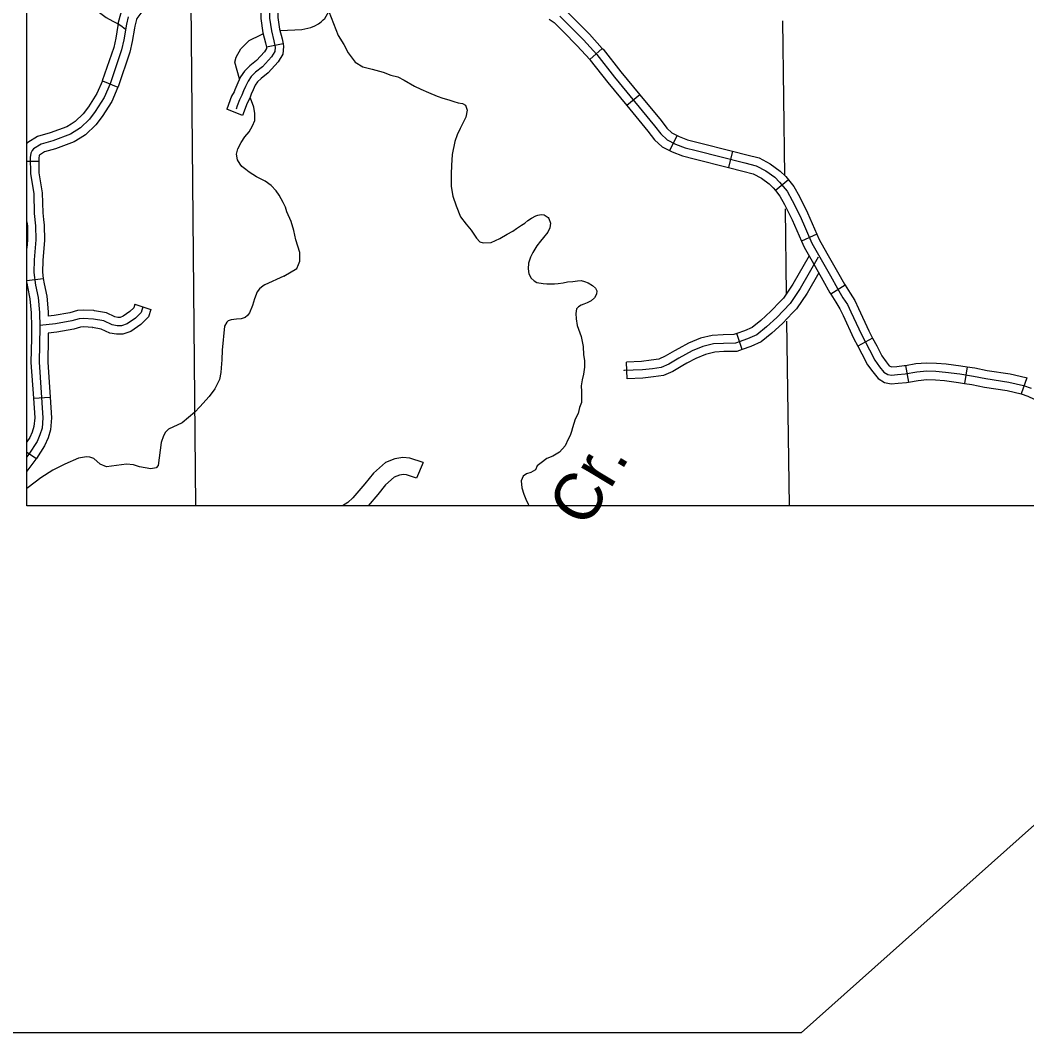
# Model space of a CAD drawing. Extents: x 1377389 to 1380723, y 1168351 to 1170484.
# Drawn here: x 1378339.4 to 1378518.7, y 1168608.3 to 1168788.5 of the extents above; entities that cross this region are included whole.
import ezdxf

# ---------------------------------------------------------------- set-up
doc = ezdxf.new("R2010")
doc.units = 0
for name, color, linetype in [('B_Contour_Elevations', 7, 'Continuous'), ('B_Fill', 7, 'Continuous'), ('B_Text', 7, 'Continuous')]:
    doc.layers.add(name, color=color, linetype=linetype)

msp = doc.modelspace()

# ---------------------------------------------------------------- linework, layer by layer
at = {"layer": 'B_Contour_Elevations'}
for q in [(1379068.4, 1169134.14), (1378016.6, 1168608.3)]:
    msp.add_line((1378478.5, 1168608.3), q, dxfattribs=at)
at = {"layer": 'B_Fill'}
for p, q in [((1378386.22, 1168784.29), (1378383.28, 1168783.71)), ((1378443.07, 1168783.5), (1378440.83, 1168781.5)), ((1378354.05, 1168777.75), (1378356.81, 1168776.57)), ((1378449.74, 1168775.25), (1378447.43, 1168773.33)), ((1378378.99, 1168771.54), (1378376.21, 1168772.67)), ((1378456.43, 1168767.97), (1378455.04, 1168765.31)), ((1378466.24, 1168765.22), (1378465.52, 1168762.3)), ((1378340.61, 1168763.4), (1378342.75, 1168763.41)), ((1378476.23, 1168760.1), (1378473.92, 1168758.18)), ((1378481.3, 1168750.42), (1378478.55, 1168749.21)), ((1378340.61, 1168742.19), (1378343.53, 1168742.56)), ((1378486.3, 1168741.35), (1378483.74, 1168739.78)), ((1378359.85, 1168737.96), (1378362.69, 1168737.02)), ((1378468, 1168729.9), (1378467.01, 1168732.73)), ((1378491.21, 1168731.91), (1378488.55, 1168730.52)), ((1378447.47, 1168724.68), (1378447.36, 1168727.68)), ((1378497.06, 1168727.07), (1378497.58, 1168724.11)), ((1378508.02, 1168726.84), (1378507.56, 1168723.87)), ((1378518.65, 1168724.86), (1378517.68, 1168722.02)), ((1378341.76, 1168721.23), (1378344.75, 1168721.44)), ((1378340.61, 1168711.63), (1378342.29, 1168710.53))]:
    msp.add_line(p, q, dxfattribs=at)
for points in [[(1378370.69, 1168702.1), (1378369.82, 1168798.09), (1378369.77, 1168801.63)], [(1378362.4, 1168796.94), (1378362.58, 1168795.29), (1378362.53, 1168794.06), (1378362.12, 1168791.97), (1378361.65, 1168790.93), (1378360.91, 1168789.75), (1378360.2, 1168788.83), (1378360.11, 1168788.62), (1378359.82, 1168787.47), (1378359.75, 1168787.07)], [(1378384.73, 1168795.78), (1378382.98, 1168793.54), (1378382.28, 1168791.51), (1378382.29, 1168788.79), (1378382.64, 1168786.29), (1378383.12, 1168784.51), (1378383.28, 1168783.71)], [(1378385.31, 1168794.04), (1378384.34, 1168792.8), (1378383.81, 1168791.26), (1378383.82, 1168788.9), (1378384.14, 1168786.6), (1378384.6, 1168784.86), (1378384.83, 1168783.74), (1378384.75, 1168782.96), (1378384.15, 1168781.98), (1378382.56, 1168780.21), (1378381.33, 1168779.27), (1378380.53, 1168778.47), (1378379.99, 1168777.67), (1378379.56, 1168776.71), (1378379.2, 1168775.93), (1378378.88, 1168775.15), (1378378.47, 1168774.35), (1378378.07, 1168773.29), (1378377.87, 1168772.67)], [(1378386.89, 1168793.67), (1378385.65, 1168792.09), (1378385.28, 1168791.01), (1378385.29, 1168789), (1378385.59, 1168786.89), (1378386.04, 1168785.19), (1378386.22, 1168784.29)], [(1378352, 1168791.72), (1378353.3, 1168790.09), (1378354.75, 1168788.98), (1378355.92, 1168788.35), (1378356.96, 1168787.81), (1378357.56, 1168787.37), (1378358.18, 1168786.91)], [(1378394.17, 1168792.5), (1378394.07, 1168791.32), (1378394.35, 1168790.08), (1378396.01, 1168785.78)], [(1378358.04, 1168790.94), (1378357.59, 1168790.36), (1378357.26, 1168789.58), (1378356.88, 1168788.08), (1378356.79, 1168787.55)], [(1378385.74, 1168786.67), (1378389.55, 1168786.83), (1378391.19, 1168787.24), (1378391.86, 1168787.5), (1378392.51, 1168787.85), (1378393.02, 1168788.22), (1378393.39, 1168788.59), (1378393.65, 1168788.82), (1378394.35, 1168790.08)], [(1378435.36, 1168791.17), (1378436.47, 1168790.38), (1378438.24, 1168788.6), (1378440.8, 1168786.03), (1378443.07, 1168783.5)], [(1378358.66, 1168789.11), (1378358.32, 1168787.78), (1378357.88, 1168785.02), (1378357.48, 1168783.25), (1378355.41, 1168777.18), (1378354.39, 1168774.77), (1378352.78, 1168772.26), (1378351.74, 1168770.89), (1378350.13, 1168769.35), (1378348.37, 1168768.23), (1378345.23, 1168767.07), (1378343.12, 1168766.48), (1378341.77, 1168765.64), (1378341.52, 1168765.3), (1378341.32, 1168764.82), (1378341.21, 1168764.08), (1378341.23, 1168761.21), (1378341.82, 1168757.64), (1378341.93, 1168754.14), (1378342.16, 1168751.94), (1378342.2, 1168749.4), (1378341.93, 1168745.85), (1378341.86, 1168743.61), (1378342.15, 1168741.33), (1378342.62, 1168739.17), (1378342.85, 1168736.51), (1378342.91, 1168733.91), (1378342.8, 1168727.63), (1378343.47, 1168717.75), (1378343.3, 1168715.9), (1378342.94, 1168714.7), (1378342.41, 1168713.51), (1378340.93, 1168711.25), (1378340.61, 1168710.82)], [(1378433.63, 1168788.72), (1378434.52, 1168788.09), (1378436.11, 1168786.48), (1378438.62, 1168783.97), (1378440.83, 1168781.5)], [(1378435.51, 1168789.26), (1378437.19, 1168787.56), (1378439.74, 1168785.02), (1378442.08, 1168782.4), (1378445.22, 1168778.4), (1378452.39, 1168769.74), (1378453.49, 1168768.28), (1378454.63, 1168767.24), (1378456.13, 1168766.46), (1378457.81, 1168765.82), (1378459.81, 1168765.3), (1378468.46, 1168763.15), (1378470.48, 1168762.61), (1378472.2, 1168761.73), (1378473.8, 1168760.55), (1378474.64, 1168759.71), (1378475.98, 1168758.09), (1378476.88, 1168756.45), (1378478.29, 1168753.63), (1378480.4, 1168748.81), (1378481.78, 1168746.35), (1378483.69, 1168742.99), (1378484.93, 1168740.77), (1378485.93, 1168739.13), (1378486.73, 1168737.91), (1378487.34, 1168736.59), (1378489.2, 1168732.59), (1378490.63, 1168729.84), (1378491.61, 1168728), (1378492.45, 1168726.82), (1378493.19, 1168725.88), (1378493.89, 1168725.46), (1378494.57, 1168725.33), (1378495.63, 1168725.43), (1378497.03, 1168725.57), (1378499.1, 1168725.93), (1378500.84, 1168726.09), (1378502.48, 1168726.03), (1378504.17, 1168725.89), (1378506.71, 1168725.55), (1378509.16, 1168725.17), (1378511.36, 1168724.73), (1378515.44, 1168724.12), (1378518.09, 1168723.5), (1378519.43, 1168723.04)], [(1378475.14, 1168788.42), (1378475.52, 1168760.9)], [(1378356.79, 1168787.55), (1378356.43, 1168785.29), (1378356.06, 1168783.65), (1378354.03, 1168777.71)], [(1378359.75, 1168787.07), (1378359.38, 1168784.73), (1378358.96, 1168782.84), (1378356.84, 1168776.63), (1378356.81, 1168776.57)], [(1378378.45, 1168778.09), (1378377.64, 1168781.06), (1378377.88, 1168781.94), (1378378.69, 1168783.39), (1378380.17, 1168784.91), (1378382.25, 1168785.93), (1378382.6, 1168786.1)], [(1378396.01, 1168785.78), (1378397.06, 1168784.17), (1378397.81, 1168782.73), (1378399.06, 1168781.06), (1378400.44, 1168780.23), (1378402.11, 1168779.81), (1378404.05, 1168779.26), (1378405.43, 1168778.71), (1378406.68, 1168778.43), (1378407.78, 1168777.83), (1378409.6, 1168776.79), (1378410.76, 1168776.23), (1378412.12, 1168775.65), (1378413.68, 1168774.99), (1378414.7, 1168774.61), (1378415.72, 1168774.34), (1378416.61, 1168774.04), (1378417.39, 1168773.82), (1378418.15, 1168773.7), (1378418.71, 1168773.4), (1378419.01, 1168772.48), (1378418.78, 1168771.24), (1378417.75, 1168769.21), (1378417.25, 1168768.12)], [(1378383.28, 1168783.71), (1378383.28, 1168783.66), (1378383.26, 1168783.45), (1378382.92, 1168782.89), (1378381.52, 1168781.34), (1378380.32, 1168780.42), (1378379.34, 1168779.44), (1378378.65, 1168778.42), (1378378.17, 1168777.34), (1378377.8, 1168776.54), (1378377.63, 1168776.12)], [(1378386.22, 1168784.29), (1378386.31, 1168783.81), (1378386.18, 1168782.48), (1378385.34, 1168781.09), (1378383.56, 1168779.13), (1378382.3, 1168778.16), (1378381.67, 1168777.53), (1378381.28, 1168776.95), (1378380.9, 1168776.1), (1378380.55, 1168775.35), (1378380.41, 1168774.99)], [(1378443.07, 1168783.5), (1378443.21, 1168783.34), (1378446.37, 1168779.32), (1378449.74, 1168775.25)], [(1378440.83, 1168781.5), (1378440.91, 1168781.42), (1378444.03, 1168777.44), (1378447.43, 1168773.33)], [(1378354.05, 1168777.75), (1378353.08, 1168775.46), (1378351.57, 1168773.11), (1378350.64, 1168771.87), (1378349.22, 1168770.51), (1378348.48, 1168770.04)], [(1378356.81, 1168776.57), (1378355.74, 1168774.05), (1378354.04, 1168771.39), (1378352.89, 1168769.87), (1378351.07, 1168768.14), (1378350.09, 1168767.51)], [(1378377.63, 1168776.12), (1378377.49, 1168775.79), (1378377.07, 1168774.97), (1378376.21, 1168772.67)], [(1378386.38, 1168742.95), (1378388.65, 1168744.33), (1378389, 1168745.01), (1378389.18, 1168745.63), (1378389.2, 1168746.35), (1378389.2, 1168747.19), (1378388.49, 1168749.45), (1378388.17, 1168751.07), (1378387.67, 1168752.69), (1378386.88, 1168754.43), (1378386.66, 1168755.23), (1378386.22, 1168756.07), (1378385.52, 1168757.37), (1378385.02, 1168758.15), (1378384.09, 1168759.11), (1378383.01, 1168759.89), (1378382.06, 1168760.35), (1378381.48, 1168760.65), (1378380.16, 1168761.47), (1378379.58, 1168761.97), (1378378.9, 1168762.49), (1378378.57, 1168762.89), (1378378.13, 1168763.69), (1378377.95, 1168764.67), (1378378.19, 1168765.63), (1378378.74, 1168766.73), (1378379.4, 1168767.75), (1378380.2, 1168768.66), (1378380.77, 1168769.74), (1378381.17, 1168770.64), (1378381.19, 1168771.88), (1378381, 1168773.04), (1378380.44, 1168774.62), (1378380.42, 1168774.66)], [(1378380.41, 1168774.99), (1378380.22, 1168774.53), (1378379.81, 1168773.75), (1378378.99, 1168771.54)], [(1378449.74, 1168775.25), (1378453.55, 1168770.65), (1378454.59, 1168769.28), (1378455.48, 1168768.46), (1378456.43, 1168767.97)], [(1378447.43, 1168773.33), (1378451.19, 1168768.79), (1378452.36, 1168767.25), (1378453.75, 1168765.98), (1378455.04, 1168765.31)], [(1378348.48, 1168770.04), (1378347.71, 1168769.55), (1378344.77, 1168768.47), (1378342.52, 1168767.84), (1378340.76, 1168766.75), (1378340.61, 1168766.55)], [(1378417.25, 1168768.12), (1378416.83, 1168766.94), (1378416.34, 1168764.64), (1378416.2, 1168762.65), (1378416.13, 1168761.17), (1378416.15, 1168758.89), (1378416.48, 1168757.21), (1378417.02, 1168755.45), (1378417.8, 1168753.51), (1378418.85, 1168752.19), (1378419.71, 1168751.15), (1378420.67, 1168749.75), (1378421.27, 1168749.07), (1378421.87, 1168748.87), (1378423.27, 1168748.97), (1378424.82, 1168749.69), (1378426.12, 1168750.43), (1378427.13, 1168750.98), (1378427.77, 1168751.42), (1378428.71, 1168752.04), (1378429.25, 1168752.4), (1378429.78, 1168752.84), (1378430.48, 1168753.26), (1378431.22, 1168753.72), (1378431.58, 1168753.82), (1378432.16, 1168753.96), (1378432.69, 1168753.88), (1378433.43, 1168753.4), (1378433.57, 1168753.2), (1378433.84, 1168752.4), (1378433.7, 1168751.56), (1378433.36, 1168750.8), (1378432.59, 1168749.86), (1378432.05, 1168749.16), (1378431.43, 1168748.34), (1378430.68, 1168747.18)], [(1378350.09, 1168767.51), (1378349.05, 1168766.85), (1378345.7, 1168765.61), (1378343.74, 1168765.07), (1378342.85, 1168764.51), (1378342.81, 1168764.42), (1378342.74, 1168763.97), (1378342.75, 1168763.41)], [(1378456.43, 1168767.97), (1378456.74, 1168767.81), (1378458.26, 1168767.23), (1378460.17, 1168766.73), (1378466.24, 1168765.22)], [(1378455.04, 1168765.31), (1378455.51, 1168765.06), (1378457.35, 1168764.36), (1378459.43, 1168763.82), (1378465.52, 1168762.3)], [(1378466.24, 1168765.22), (1378468.83, 1168764.57), (1378471.01, 1168763.99), (1378472.97, 1168762.98), (1378474.76, 1168761.67), (1378475.73, 1168760.7), (1378476.23, 1168760.1)], [(1378342.75, 1168763.41), (1378342.76, 1168761.34), (1378343.35, 1168757.79), (1378343.46, 1168754.24), (1378343.58, 1168753.06)], [(1378465.52, 1168762.3), (1378468.08, 1168761.67), (1378469.93, 1168761.17), (1378471.39, 1168760.42), (1378472.8, 1168759.39), (1378473.51, 1168758.68), (1378473.92, 1168758.18)], [(1378476.23, 1168760.1), (1378477.2, 1168758.92), (1378478.19, 1168757.13), (1378479.62, 1168754.25), (1378481.3, 1168750.42)], [(1378473.92, 1168758.18), (1378474.71, 1168757.22), (1378475.53, 1168755.74), (1378476.9, 1168752.98), (1378478.55, 1168749.21)], [(1378475.61, 1168754.95), (1378475.82, 1168739.77)], [(1378340.61, 1168752.61), (1378340.69, 1168751.85), (1378340.72, 1168749.44), (1378340.61, 1168747.96)], [(1378343.58, 1168753.06), (1378343.69, 1168752.03), (1378343.73, 1168749.35), (1378343.45, 1168745.77), (1378343.39, 1168743.68), (1378343.53, 1168742.56)], [(1378481.3, 1168750.42), (1378481.71, 1168749.46), (1378483.06, 1168747.07), (1378484.97, 1168743.71), (1378486.2, 1168741.51), (1378486.3, 1168741.35)], [(1378478.55, 1168749.21), (1378479.03, 1168748.12), (1378480.45, 1168745.6), (1378482.35, 1168742.24), (1378483.61, 1168739.99), (1378483.74, 1168739.78)], [(1378430.68, 1168747.18), (1378430.26, 1168746.34), (1378429.94, 1168745.28), (1378429.85, 1168744.25), (1378430.01, 1168743.39), (1378430.39, 1168742.59), (1378430.91, 1168742.15), (1378431.41, 1168741.81), (1378432.53, 1168741.66), (1378433.17, 1168741.58), (1378434.54, 1168741.58), (1378435.22, 1168741.64), (1378436.1, 1168741.78), (1378436.88, 1168741.92), (1378437.84, 1168742.02), (1378438.68, 1168742.12), (1378439.29, 1168742.18), (1378439.91, 1168741.98), (1378440.57, 1168741.8), (1378441.33, 1168741.3), (1378441.83, 1168740.84), (1378442.11, 1168740.32), (1378442.06, 1168739.76), (1378441.7, 1168739.1), (1378441.06, 1168738.54), (1378440.36, 1168738.22), (1378439.78, 1168737.98), (1378439.31, 1168737.8), (1378438.83, 1168737.5), (1378438.47, 1168737.12), (1378438.33, 1168736.3), (1378438.39, 1168735.34), (1378438.58, 1168734.16), (1378439.32, 1168732.2), (1378439.69, 1168730.43), (1378439.75, 1168728.95), (1378439.89, 1168727.93), (1378439.91, 1168726.79), (1378439.72, 1168725.49), (1378439.46, 1168724.51), (1378439.31, 1168723.43), (1378439.37, 1168722.41), (1378439.39, 1168721.59), (1378439.35, 1168720.49), (1378439, 1168719.57), (1378438.76, 1168718.53), (1378438.26, 1168717.49), (1378437.75, 1168715.95), (1378437.61, 1168715.29), (1378437.37, 1168714.59), (1378436.98, 1168713.95), (1378436.45, 1168712.73), (1378435.43, 1168711.63), (1378434.25, 1168710.94)], [(1378479.9, 1168746.58), (1378477.02, 1168741.55), (1378475.34, 1168739.06), (1378474.8, 1168738.5)], [(1378481.52, 1168746.35), (1378478.32, 1168740.74), (1378476.53, 1168738.1), (1378474.14, 1168735.62), (1378472.31, 1168733.94), (1378470.58, 1168732.51), (1378468.94, 1168731.79), (1378466.77, 1168731.03), (1378464.66, 1168730.99), (1378462.88, 1168730.89), (1378461, 1168730.45), (1378459.09, 1168729.65), (1378456.7, 1168728.34), (1378454.94, 1168727.32), (1378453.57, 1168726.72), (1378451.99, 1168726.48), (1378450.2, 1168726.26), (1378446.9, 1168726.14), (1378446.9, 1168726.12)], [(1378386.38, 1168742.95), (1378382.98, 1168741.39), (1378382.67, 1168741.21), (1378382.04, 1168740.68), (1378381.62, 1168740.19), (1378381.16, 1168738.95), (1378380.76, 1168737.72), (1378380.26, 1168736.45), (1378379.9, 1168735.95), (1378379.47, 1168735.6), (1378378.77, 1168735.35), (1378377.92, 1168735.3), (1378376.96, 1168735.19), (1378376.46, 1168734.98), (1378376.23, 1168734.76), (1378375.8, 1168734.04), (1378375.38, 1168729.79), (1378375.32, 1168728.05), (1378375.22, 1168726.64), (1378375.15, 1168725.8), (1378374.89, 1168724.54), (1378374.07, 1168722.93), (1378373.07, 1168721.55), (1378371.4, 1168719.69), (1378370.54, 1168718.74)], [(1378481.61, 1168743.54), (1378479.57, 1168739.96), (1378477.68, 1168737.17), (1378476.96, 1168736.42)], [(1378340.61, 1168741.75), (1378340.7, 1168741.08), (1378341.16, 1168738.95), (1378341.38, 1168736.43), (1378341.44, 1168733.91), (1378341.4, 1168731.9)], [(1378343.53, 1168742.56), (1378343.66, 1168741.59), (1378344.13, 1168739.4), (1378344.38, 1168736.6), (1378344.4, 1168735.83)], [(1378486.3, 1168741.35), (1378487.18, 1168739.91), (1378488.03, 1168738.62), (1378488.67, 1168737.2), (1378490.52, 1168733.24), (1378491.21, 1168731.91)], [(1378483.74, 1168739.78), (1378484.64, 1168738.31), (1378485.39, 1168737.16), (1378485.95, 1168735.95), (1378487.83, 1168731.91), (1378488.55, 1168730.52)], [(1378361.27, 1168737.49), (1378360.95, 1168736.51), (1378359.93, 1168735.5), (1378358.45, 1168734.45), (1378357.44, 1168734.13), (1378356.68, 1168734.13), (1378355.81, 1168734.27), (1378354.29, 1168735), (1378352.45, 1168735.32), (1378350.64, 1168735.43), (1378349.89, 1168735.36), (1378348.62, 1168735), (1378345.69, 1168734.45), (1378342.91, 1168734.17)], [(1378359.85, 1168737.96), (1378359.63, 1168737.32), (1378358.96, 1168736.65), (1378357.77, 1168735.81), (1378357.2, 1168735.63), (1378356.8, 1168735.63), (1378356.27, 1168735.72), (1378354.76, 1168736.44), (1378352.63, 1168736.81), (1378352.51, 1168736.82)], [(1378474.8, 1168738.5), (1378473.08, 1168736.71), (1378471.31, 1168735.09), (1378469.77, 1168733.83), (1378468.38, 1168733.21), (1378467.01, 1168732.73)], [(1378352.51, 1168736.82), (1378350.62, 1168736.93), (1378349.61, 1168736.84), (1378348.28, 1168736.46), (1378345.48, 1168735.94), (1378344.4, 1168735.83)], [(1378362.69, 1168737.02), (1378362.26, 1168735.7), (1378360.9, 1168734.35), (1378359.13, 1168733.1), (1378357.67, 1168732.63), (1378356.56, 1168732.63), (1378355.36, 1168732.83), (1378353.83, 1168733.55), (1378352.28, 1168733.83), (1378352.33, 1168733.83)], [(1378476.96, 1168736.42), (1378475.17, 1168734.56), (1378473.28, 1168732.82), (1378471.36, 1168731.25), (1378469.49, 1168730.42), (1378468, 1168729.9)], [(1378352.33, 1168733.83), (1378350.67, 1168733.93), (1378350.16, 1168733.88), (1378348.96, 1168733.53), (1378345.91, 1168732.97), (1378344.42, 1168732.81)], [(1378475.89, 1168734.93), (1378476.35, 1168702.1)], [(1378344.42, 1168732.81), (1378344.4, 1168731.85)], [(1378467.01, 1168732.73), (1378466.5, 1168732.55), (1378464.6, 1168732.52), (1378462.66, 1168732.41), (1378460.53, 1168731.91), (1378458.43, 1168731.02), (1378456.71, 1168730.09)], [(1378341.4, 1168731.9), (1378341.32, 1168727.59), (1378341.76, 1168721.23)], [(1378344.4, 1168731.85), (1378344.33, 1168727.66), (1378344.75, 1168721.44)], [(1378488.55, 1168730.52), (1378489.28, 1168729.13), (1378490.31, 1168727.2), (1378491.23, 1168725.91), (1378492.17, 1168724.72), (1378493.33, 1168724.02), (1378494.49, 1168723.78), (1378495.78, 1168723.91), (1378497.24, 1168724.05), (1378497.58, 1168724.11)], [(1378491.21, 1168731.91), (1378491.93, 1168730.53), (1378492.86, 1168728.78), (1378493.63, 1168727.71), (1378494.18, 1168727.01), (1378494.44, 1168726.86), (1378494.65, 1168726.81), (1378495.49, 1168726.89), (1378496.83, 1168727.03), (1378497.06, 1168727.07)], [(1378456.71, 1168730.09), (1378455.95, 1168729.67), (1378454.25, 1168728.69), (1378453.14, 1168728.2), (1378451.78, 1168727.99), (1378450.07, 1168727.78), (1378447.36, 1168727.68)], [(1378468, 1168729.9), (1378467.04, 1168729.56), (1378464.71, 1168729.52), (1378463.09, 1168729.43), (1378461.46, 1168729.04), (1378459.73, 1168728.32), (1378458.15, 1168727.46)], [(1378458.15, 1168727.46), (1378457.42, 1168727.06), (1378455.61, 1168726.01), (1378453.98, 1168725.29), (1378452.19, 1168725.02), (1378450.31, 1168724.79), (1378447.47, 1168724.68)], [(1378497.06, 1168727.07), (1378498.91, 1168727.39), (1378500.8, 1168727.56), (1378502.56, 1168727.5), (1378504.33, 1168727.36), (1378506.92, 1168727.01), (1378508.02, 1168726.84)], [(1378508.02, 1168726.84), (1378509.42, 1168726.62), (1378511.62, 1168726.19), (1378515.71, 1168725.56), (1378518.5, 1168724.92), (1378518.65, 1168724.86)], [(1378497.58, 1168724.11), (1378499.3, 1168724.41), (1378500.88, 1168724.56), (1378502.39, 1168724.5), (1378504.01, 1168724.37), (1378506.49, 1168724.04), (1378507.56, 1168723.87)], [(1378507.56, 1168723.87), (1378508.9, 1168723.67), (1378511.1, 1168723.23), (1378515.15, 1168722.62), (1378517.67, 1168722.03), (1378517.68, 1168722.02)], [(1378344.75, 1168721.44), (1378345.01, 1168717.73), (1378344.81, 1168715.61), (1378344.37, 1168714.17), (1378343.76, 1168712.78), (1378342.29, 1168710.53)], [(1378517.68, 1168722.02), (1378518.85, 1168721.62), (1378520.98, 1168720.6), (1378523.78, 1168719.03), (1378526.97, 1168717.46)], [(1378341.76, 1168721.23), (1378342, 1168717.77), (1378341.85, 1168716.19), (1378341.55, 1168715.21), (1378341.12, 1168714.22), (1378340.61, 1168713.45)], [(1378370.54, 1168718.74), (1378368.27, 1168716.85), (1378365.83, 1168715.74), (1378365.28, 1168715.19), (1378364.91, 1168714.53), (1378364.52, 1168713.36), (1378363.96, 1168709.23), (1378363.65, 1168708.83), (1378362.65, 1168708.65), (1378360.63, 1168709.03), (1378359.57, 1168709.38), (1378358.36, 1168709.52), (1378354.76, 1168709), (1378353.67, 1168709.47), (1378352.5, 1168710.49), (1378351.84, 1168710.72), (1378351.2, 1168710.78), (1378349.82, 1168710.54), (1378347.34, 1168709.51), (1378345.2, 1168708.4), (1378343.08, 1168707.05), (1378340.81, 1168705.34), (1378340.61, 1168705.17)], [(1378342.29, 1168710.53), (1378342.18, 1168710.38), (1378340.61, 1168708.25)], [(1378411.19, 1168709.77), (1378408.82, 1168710.54), (1378407.55, 1168710.68), (1378406.15, 1168710.42), (1378404.45, 1168709.8), (1378402.31, 1168707.9), (1378400.81, 1168706.02), (1378398.66, 1168703.52), (1378397.75, 1168702.67), (1378396.83, 1168702.1)], [(1378434.25, 1168710.94), (1378433.17, 1168710.53), (1378432.19, 1168709.75), (1378431.5, 1168709.17), (1378431.18, 1168708.49), (1378430.32, 1168707.99), (1378429.58, 1168707.79), (1378428.99, 1168707.37), (1378428.63, 1168706.53), (1378428.75, 1168705.31), (1378429.08, 1168704.17), (1378429.6, 1168702.99), (1378429.8, 1168702.53), (1378429.96, 1168702.1)], [(1378411.19, 1168709.77), (1378409.99, 1168707.01)], [(1378409.99, 1168707.01), (1378408.19, 1168707.59), (1378407.66, 1168707.65), (1378406.95, 1168707.51), (1378406.01, 1168707.17), (1378404.49, 1168705.83), (1378403.12, 1168704.1), (1378401.39, 1168702.1)]]:
    msp.add_lwpolyline(points, dxfattribs=at)
at = {"layer": 'B_Text'}
msp.add_lwpolyline([(1378340.61, 1169579.43), (1379848.03, 1169579.43), (1379848.03, 1168702.1), (1378340.61, 1168702.1)], close=True, dxfattribs=at)

# ---------------------------------------------------------------- texts
at = {"layer": 'B_Fill'}
msp.add_text('Cr.', height=8.448, rotation=58.9985, dxfattribs=at).set_placement((1378440.28, 1168697.89))

doc.saveas('drawing.dxf')
